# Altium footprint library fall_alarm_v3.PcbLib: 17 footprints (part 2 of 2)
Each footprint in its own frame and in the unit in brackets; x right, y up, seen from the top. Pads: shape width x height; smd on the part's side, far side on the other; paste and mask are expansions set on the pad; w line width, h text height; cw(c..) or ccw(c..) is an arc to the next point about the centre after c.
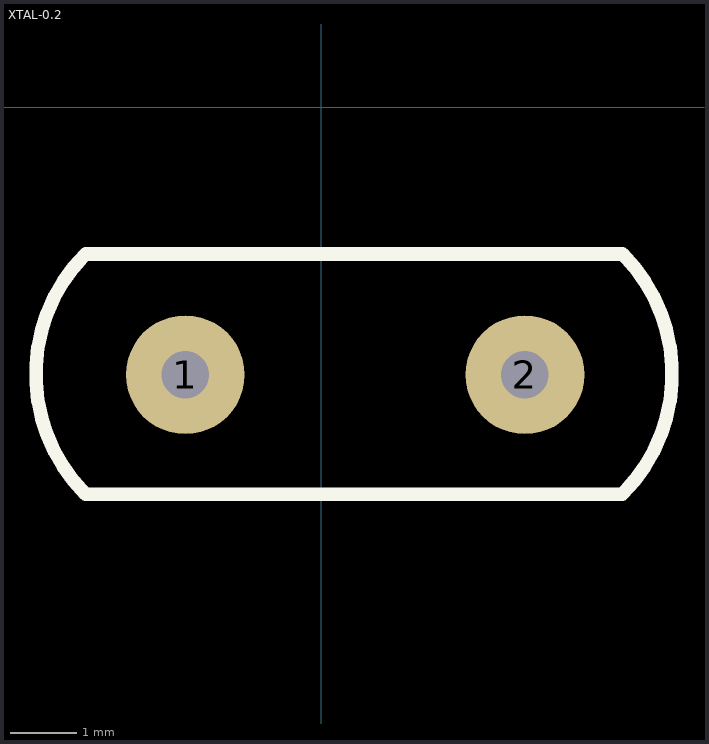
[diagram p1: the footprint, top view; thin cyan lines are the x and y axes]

## XTAL-0.2 [mil]
height 149.61
pads (2):
  round 70 hole 28: 1(-79.92,-157.48) 2(120.08,-157.48)
Top Overlay:
  lines w8: 177.41,-227.79 -138.63,-227.79 cw(c-67.92,-157.08) -138.63,-86.37 177.41,-86.37 ; 177.48,-227.72 ccw(c106.77,-157.01) 177.48,-86.3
